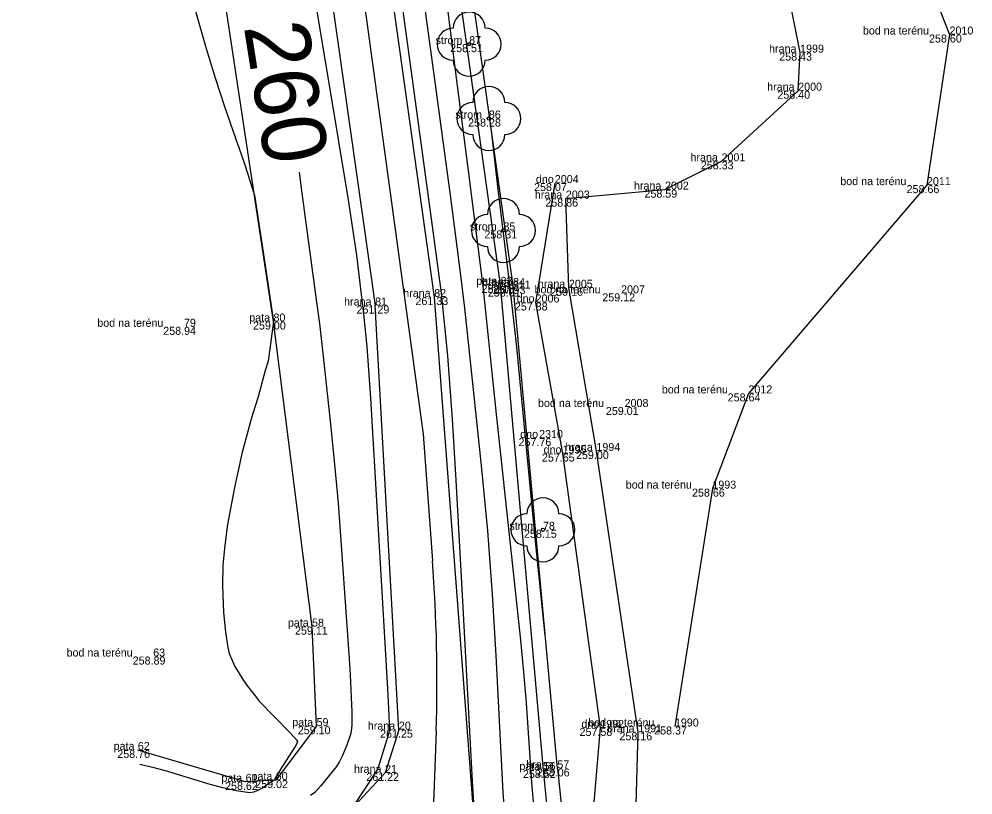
# Model space of a CAD drawing. Extents: x -567962 to -566460, y -1093720 to -1089838.
# Drawn here: x -567551.2 to -567491.6, y -1093494.7 to -1093446.2 of the extents above; entities that cross this region are included whole.
import ezdxf

# ---------------------------------------------------------------- set-up
doc = ezdxf.new("R2010")
doc.units = 0
for name, color, linetype in [('0_osa hráze', 7, 'Continuous'), ('bod_znacka', 7, 'Continuous'), ('cislo_bodu', 7, 'Continuous'), ('Doměření - kraj pole', 7, 'Continuous'), ('hlavni_vrst', 7, 'Continuous'), ('hrana_L', 7, 'Continuous'), ('kod_bodu', 7, 'Continuous'), ('norm_vrst', 7, 'Continuous'), ('Popis_hl_vrs', 7, 'Continuous'), ('stromy', 7, 'Continuous'), ('vyska_bodu', 7, 'Continuous')]:
    doc.layers.add(name, color=color, linetype=linetype)

msp = doc.modelspace()

# ---------------------------------------------------------------- linework, layer by layer
at = {"layer": '0_osa hráze'}
for points in [[(-567540.529, -1093385.133), (-567538.25, -1093394.72), (-567535.173, -1093410.402), (-567530.931, -1093435.726), (-567525.971, -1093472.155), (-567525.379, -1093480.069)], [(-567525.15, -1093490.7), (-567525.61, -1093503.034)]]:
    msp.add_lwpolyline(points, dxfattribs=at)
msp.add_arc((-567625.099, -1093487.535), 100, 358.18581, 4.28156, dxfattribs=at)
at = {"layer": 'bod_znacka'}
for p, q in [((-567493.09, -1093447.18), (-567493.09, -1093447.18)), ((-567523.09, -1093447.78), (-567523.09, -1093447.78)), ((-567502.42, -1093448.31), (-567502.42, -1093448.31)), ((-567502.54, -1093450.69), (-567502.54, -1093450.69)), ((-567521.86, -1093452.43), (-567521.86, -1093452.43)), ((-567507.33, -1093455.1), (-567507.33, -1093455.1)), ((-567517.74, -1093456.46), (-567517.74, -1093456.46)), ((-567494.5, -1093456.59), (-567494.5, -1093456.59)), ((-567510.86, -1093456.87), (-567510.86, -1093456.87)), ((-567517.05, -1093457.43), (-567517.05, -1093457.43)), ((-567520.95, -1093459.42), (-567520.95, -1093459.42)), ((-567521.13, -1093462.82), (-567521.13, -1093462.82)), ((-567520.74, -1093463.05), (-567520.74, -1093463.05)), ((-567520.34, -1093462.89), (-567520.34, -1093462.89)), ((-567516.86, -1093463), (-567516.86, -1093463)), ((-567525.27, -1093463.58), (-567525.27, -1093463.58)), ((-567513.6, -1093463.35), (-567513.6, -1093463.35)), ((-567528.96, -1093464.11), (-567528.96, -1093464.11)), ((-567518.94, -1093463.92), (-567518.94, -1093463.92)), ((-567540.9, -1093465.44), (-567540.9, -1093465.44)), ((-567535.31, -1093465.11), (-567535.31, -1093465.11)), ((-567505.65, -1093469.6), (-567505.65, -1093469.6)), ((-567513.38, -1093470.45), (-567513.38, -1093470.45)), ((-567518.72, -1093472.39), (-567518.72, -1093472.39)), ((-567517.26, -1093473.36), (-567517.26, -1093473.36)), ((-567515.14, -1093473.2), (-567515.14, -1093473.2)), ((-567507.9, -1093475.55), (-567507.9, -1093475.55)), ((-567518.48, -1093478.12), (-567518.48, -1093478.12)), ((-567532.9, -1093484.17), (-567532.9, -1093484.17)), ((-567542.82, -1093486.04), (-567542.82, -1093486.04)), ((-567532.62, -1093490.39), (-567532.62, -1093490.39)), ((-567527.48, -1093490.61), (-567527.48, -1093490.61)), ((-567514.9, -1093490.5), (-567514.9, -1093490.5)), ((-567510.24, -1093490.41), (-567510.24, -1093490.41)), ((-567512.53, -1093490.77), (-567512.53, -1093490.77)), ((-567543.78, -1093491.88), (-567543.78, -1093491.88)), ((-567517.58, -1093493.03), (-567517.58, -1093493.03)), ((-567528.34, -1093493.31), (-567528.34, -1093493.31)), ((-567518.44, -1093493.13), (-567518.44, -1093493.13)), ((-567537.05, -1093493.87), (-567537.05, -1093493.87)), ((-567535.17, -1093493.76), (-567535.17, -1093493.76))]:
    msp.add_line(p, q, dxfattribs=at)
at = {"layer": 'Doměření - kraj pole'}
msp.add_lwpolyline([(-567511.32, -1093424.48), (-567499.33, -1093435.21), (-567496.49, -1093438.53), (-567493.09, -1093447.18), (-567494.5, -1093456.59), (-567505.65, -1093469.6), (-567507.9, -1093475.55), (-567510.24, -1093490.41)], dxfattribs=at)
at = {"layer": 'hlavni_vrst'}
for points in [[(-567520.857, -1093495.898), (-567520.969, -1093494.533), (-567521.405, -1093485.968), (-567521.634, -1093482.149), (-567521.922, -1093478.193), (-567522.287, -1093474.31), (-567522.919, -1093468.372), (-567523.366, -1093464.276), (-567523.59, -1093462.375), (-567524.258, -1093457.209), (-567525.412, -1093448.608), (-567526.367, -1093441.597)], [(-567533.712, -1093455.786), (-567533.528, -1093457.088), (-567532.613, -1093463.894), (-567532.439, -1093465.24), (-567532.156, -1093467.671), (-567531.765, -1093471.327), (-567531.517, -1093473.816), (-567531.279, -1093476.461), (-567531.033, -1093479.682), (-567530.587, -1093486.192), (-567530.528, -1093487.176), (-567530.42, -1093489.511), (-567530.41, -1093489.891), (-567530.411, -1093490.279), (-567530.427, -1093490.564), (-567530.502, -1093490.91), (-567530.726, -1093491.58), (-567531.025, -1093492.266), (-567531.206, -1093492.63), (-567531.38, -1093492.919), (-567532.382, -1093494.142), (-567532.728, -1093494.526), (-567532.992, -1093494.72)]]:
    msp.add_lwpolyline(points, dxfattribs=at)
at = {"layer": 'hrana_L'}
for p, q in [((-567520.34, -1093462.89), (-567524.37, -1093434.07)), ((-567521.13, -1093462.82), (-567525.14, -1093434.33)), ((-567529.2, -1093435.47), (-567525.27, -1093463.58)), ((-567532.94, -1093436.03), (-567528.96, -1093464.11)), ((-567535.31, -1093465.11), (-567539.55, -1093437.04)), ((-567518.44, -1093493.13), (-567521.13, -1093462.82)), ((-567517.58, -1093493.03), (-567520.34, -1093462.89)), ((-567525.27, -1093463.58), (-567522.86, -1093495.41)), ((-567527.48, -1093490.61), (-567528.96, -1093464.11)), ((-567532.9, -1093484.17), (-567535.31, -1093465.11)), ((-567532.62, -1093490.39), (-567532.9, -1093484.17)), ((-567532.62, -1093490.39), (-567535.17, -1093493.76)), ((-567527.48, -1093490.61), (-567528.34, -1093493.31)), ((-567537.05, -1093493.87), (-567543.78, -1093491.88)), ((-567517.58, -1093493.03), (-567517.03, -1093498.2)), ((-567530.22, -1093495.35), (-567528.34, -1093493.31)), ((-567517.94, -1093498.39), (-567518.44, -1093493.13)), ((-567535.17, -1093493.76), (-567537.05, -1093493.87))]:
    msp.add_line(p, q, dxfattribs=at)
for points in [[(-567512.79, -1093499.42), (-567512.53, -1093490.77), (-567515.14, -1093473.2), (-567516.86, -1093463), (-567517.05, -1093457.43), (-567510.86, -1093456.87), (-567507.33, -1093455.1), (-567502.54, -1093450.69), (-567502.42, -1093448.31), (-567503.88, -1093440.95), (-567522.38, -1093412.95), (-567526.32, -1093385.81), (-567534.77, -1093360.4), (-567542.63, -1093336.01), (-567576.2, -1093233.72), (-567608.17, -1093145.58), (-567635.77, -1093066.14), (-567667.57, -1092974.74), (-567711.16, -1092852.65), (-567720.26, -1092825.93), (-567727.08, -1092790.56), (-567728.5, -1092756.42), (-567723.8, -1092688.57)], [(-567517.74, -1093456.46), (-567518.94, -1093463.92), (-567517.26, -1093473.36), (-567514.9, -1093490.5), (-567515.65, -1093499.33)]]:
    msp.add_lwpolyline(points, dxfattribs=at)
at = {"layer": 'norm_vrst'}
for points in [[(-567519.07, -1093495.113), (-567519.185, -1093493.899), (-567519.505, -1093488.936), (-567519.674, -1093487.013), (-567519.863, -1093485.026), (-567520.291, -1093480.961), (-567521.381, -1093470.896), (-567522.219, -1093462.897), (-567523.058, -1093456.17), (-567523.962, -1093449.25), (-567526.239, -1093431.121)], [(-567522.779, -1093495.509), (-567522.886, -1093493.83), (-567523.482, -1093482.571), (-567523.901, -1093475.03), (-567524.13, -1093471.219), (-567524.428, -1093467.245), (-567524.823, -1093463.334), (-567525.265, -1093459.925), (-567526.681, -1093449.508), (-567528.129, -1093439.024)], [(-567532.787, -1093444.583), (-567531.262, -1093453.732), (-567530.67, -1093457.389), (-567530.134, -1093460.956), (-567529.918, -1093462.718), (-567529.694, -1093464.648), (-567529.477, -1093466.669), (-567529.242, -1093469.894), (-567528.191, -1093488.065), (-567528.098, -1093489.721), (-567528.078, -1093490.236), (-567528.073, -1093490.599), (-567528.14, -1093490.95), (-567528.773, -1093492.98), (-567528.799, -1093493.036), (-567528.989, -1093493.346), (-567530.274, -1093495.303)], [(-567540.303, -1093445.293), (-567539.506, -1093448.049), (-567538.942, -1093449.891), (-567538.358, -1093451.683), (-567537.683, -1093453.646), (-567537.449, -1093454.296), (-567537.144, -1093455.204), (-567536.501, -1093457.222), (-567535.829, -1093461.619), (-567535.31, -1093465.11), (-567535.65, -1093467.581), (-567535.821, -1093468.166), (-567536.265, -1093469.818), (-567536.599, -1093470.865), (-567536.747, -1093471.356), (-567537.124, -1093472.756), (-567537.257, -1093473.282), (-567537.494, -1093474.326), (-567537.714, -1093475.379), (-567537.977, -1093476.693), (-567538.18, -1093477.786), (-567538.343, -1093479.082), (-567538.48, -1093480.329), (-567538.484, -1093481.594), (-567538.435, -1093483.279), (-567538.302, -1093484.519), (-567538.155, -1093485.469), (-567538.07, -1093485.846), (-567537.727, -1093486.671), (-567537.174, -1093487.545), (-567536.924, -1093487.89), (-567536.363, -1093488.599), (-567536.22, -1093488.8), (-567534.282, -1093490.79), (-567533.872, -1093491.241), (-567533.808, -1093491.347), (-567533.842, -1093491.46), (-567533.912, -1093491.608), (-567534.797, -1093492.947), (-567535.233, -1093493.687), (-567535.272, -1093493.766), (-567535.505, -1093493.905), (-567535.982, -1093494.234), (-567536.32, -1093494.423), (-567536.558, -1093494.518), (-567536.795, -1093494.549), (-567537.649, -1093494.424), (-567538.551, -1093494.231), (-567539.408, -1093493.995), (-567541.91, -1093493.226), (-567542.762, -1093492.989), (-567543.645, -1093492.782)], [(-567518.341, -1093484.718), (-567518.936, -1093478.834), (-567520.102, -1093466.719), (-567520.543, -1093462.837), (-567521.288, -1093456.67), (-567521.697, -1093453.185)]]:
    msp.add_lwpolyline(points, dxfattribs=at)
at = {"layer": 'stromy'}
for centre in [(-567523.09, -1093447.78), (-567521.86, -1093452.43), (-567520.95, -1093459.42), (-567518.48, -1093478.12)]:
    msp.add_circle(centre, 0.1, dxfattribs=at)
for centre, start, end in [((-567523.09, -1093446.78), 0, 180), ((-567524.09, -1093447.78), 90, 270), ((-567522.09, -1093447.78), 270, 90), ((-567523.09, -1093448.78), 180, 0), ((-567521.86, -1093451.43), 0, 180), ((-567522.86, -1093452.43), 90, 270), ((-567520.86, -1093452.43), 270, 90), ((-567521.86, -1093453.43), 180, 0), ((-567520.95, -1093458.42), 0, 180), ((-567521.95, -1093459.42), 90, 270), ((-567519.95, -1093459.42), 270, 90), ((-567520.95, -1093460.42), 180, 0), ((-567518.48, -1093477.12), 0, 180), ((-567519.48, -1093478.12), 90, 270), ((-567517.48, -1093478.12), 270, 90), ((-567518.48, -1093479.12), 180, 0)]:
    msp.add_arc(centre, 1, start, end, dxfattribs=at)

# ---------------------------------------------------------------- texts
at = {"layer": 'cislo_bodu'}
for s, p in [('2010', (-567493.09, -1093447.18)), ('87', (-567523.09, -1093447.78)), ('1999', (-567502.42, -1093448.31)), ('2000', (-567502.54, -1093450.69)), ('86', (-567521.86, -1093452.43)), ('2001', (-567507.33, -1093455.1)), ('2004', (-567517.74, -1093456.46)), ('2011', (-567494.5, -1093456.59)), ('2002', (-567510.86, -1093456.87)), ('2003', (-567517.05, -1093457.43)), ('85', (-567520.95, -1093459.42)), ('83', (-567521.13, -1093462.82)), ('2311', (-567520.74, -1093463.05)), ('84', (-567520.34, -1093462.89)), ('2005', (-567516.86, -1093463)), ('82', (-567525.27, -1093463.58)), ('2007', (-567513.6, -1093463.35)), ('81', (-567528.96, -1093464.11)), ('2006', (-567518.94, -1093463.92)), ('79', (-567540.9, -1093465.44)), ('80', (-567535.31, -1093465.11)), ('2012', (-567505.65, -1093469.6)), ('2008', (-567513.38, -1093470.45)), ('2310', (-567518.72, -1093472.39)), ('1994', (-567515.14, -1093473.2)), ('1995', (-567517.26, -1093473.36)), ('1993', (-567507.9, -1093475.55)), ('78', (-567518.48, -1093478.12)), ('58', (-567532.9, -1093484.17)), ('63', (-567542.82, -1093486.04)), ('59', (-567532.62, -1093490.39)), ('1992', (-567514.9, -1093490.5)), ('1990', (-567510.24, -1093490.41)), ('20', (-567527.48, -1093490.61)), ('1991', (-567512.53, -1093490.77)), ('62', (-567543.78, -1093491.88)), ('21', (-567528.34, -1093493.31)), ('56', (-567518.44, -1093493.13)), ('57', (-567517.58, -1093493.03)), ('61', (-567537.05, -1093493.87)), ('60', (-567535.17, -1093493.76))]:
    msp.add_text(s, height=0.5, dxfattribs=at).set_placement(p)
at = {"layer": 'kod_bodu'}
for s, p in [('bod na terénu', (-567498.499, -1093447.18)), ('strom', (-567525.184, -1093447.78)), ('hrana', (-567504.357, -1093448.31)), ('hrana', (-567504.477, -1093450.69)), ('strom', (-567523.954, -1093452.43)), ('hrana', (-567509.267, -1093455.1)), ('dno', (-567518.921, -1093456.46)), ('bod na terénu', (-567499.909, -1093456.59)), ('hrana', (-567512.797, -1093456.87)), ('hrana', (-567518.987, -1093457.43)), ('strom', (-567523.044, -1093459.42)), ('pata', (-567522.642, -1093462.82)), ('hrana', (-567522.277, -1093462.89)), ('dno', (-567521.921, -1093463.05)), ('hrana', (-567518.797, -1093463)), ('hrana', (-567527.207, -1093463.58)), ('bod na terénu', (-567519.009, -1093463.35)), ('hrana', (-567530.897, -1093464.11)), ('dno', (-567520.121, -1093463.92)), ('bod na terénu', (-567546.309, -1093465.44)), ('pata', (-567536.822, -1093465.11)), ('bod na terénu', (-567511.059, -1093469.6)), ('bod na terénu', (-567518.789, -1093470.45)), ('dno', (-567519.901, -1093472.39)), ('hrana', (-567517.077, -1093473.2)), ('dno', (-567518.441, -1093473.36)), ('bod na terénu', (-567513.309, -1093475.55)), ('strom', (-567520.574, -1093478.12)), ('pata', (-567534.412, -1093484.17)), ('bod na terénu', (-567548.229, -1093486.04)), ('pata', (-567534.132, -1093490.39)), ('hrana', (-567529.417, -1093490.61)), ('dno', (-567516.081, -1093490.5)), ('bod na terénu', (-567515.649, -1093490.41)), ('hrana', (-567514.467, -1093490.77)), ('pata', (-567545.292, -1093491.88)), ('hrana', (-567530.277, -1093493.31)), ('pata', (-567519.952, -1093493.13)), ('hrana', (-567519.517, -1093493.03)), ('pata', (-567538.562, -1093493.87)), ('pata', (-567536.682, -1093493.76))]:
    msp.add_text(s, height=0.5, dxfattribs=at).set_placement(p)
at = {"layer": 'Popis_hl_vrs'}
msp.add_text('260', height=4, rotation=278.96559, dxfattribs=at).set_placement((-567537.168, -1093446.67))
at = {"layer": 'vyska_bodu'}
for s, p in [('258.60', (-567494.369, -1093447.68)), ('258.51', (-567524.275, -1093448.28)), ('258.43', (-567503.725, -1093448.81)), ('258.40', (-567503.843, -1093451.19)), ('258.28', (-567523.153, -1093452.93)), ('258.33', (-567508.623, -1093455.6)), ('258.07', (-567519.033, -1093456.96)), ('258.66', (-567495.77, -1093457.09)), ('258.59', (-567512.141, -1093457.37)), ('258.86', (-567518.331, -1093457.93)), ('258.31', (-567522.135, -1093459.92)), ('258.18', (-567522.315, -1093463.32)), ('258.01', (-567521.923, -1093463.55)), ('257.93', (-567521.623, -1093463.39)), ('259.16', (-567518.021, -1093463.5)), ('261.33', (-567526.443, -1093464.08)), ('259.12', (-567514.773, -1093463.85)), ('261.29', (-567530.121, -1093464.61)), ('257.88', (-567520.235, -1093464.42)), ('258.94', (-567542.193, -1093465.94)), ('259.00', (-567536.587, -1093465.61)), ('258.64', (-567506.943, -1093470.1)), ('259.01', (-567514.551, -1093470.95)), ('257.76', (-567520.005, -1093472.89)), ('257.65', (-567518.543, -1093473.86)), ('259.00', (-567516.417, -1093473.7)), ('258.66', (-567509.17, -1093476.05)), ('258.15', (-567519.665, -1093478.62)), ('259.11', (-567533.965, -1093484.67)), ('258.89', (-567544.101, -1093486.54)), ('259.10', (-567533.791, -1093490.89)), ('261.25', (-567528.653, -1093491.11)), ('257.58', (-567516.195, -1093491)), ('258.37', (-567511.535, -1093490.91)), ('258.16', (-567513.703, -1093491.27)), ('258.76', (-567545.063, -1093492.38)), ('258.06', (-567518.859, -1093493.53)), ('261.22', (-567529.513, -1093493.81)), ('258.52', (-567519.733, -1093493.63)), ('258.62', (-567538.331, -1093494.37)), ('259.02', (-567536.449, -1093494.26))]:
    msp.add_text(s, height=0.5, dxfattribs=at).set_placement(p)

doc.saveas('drawing.dxf')
